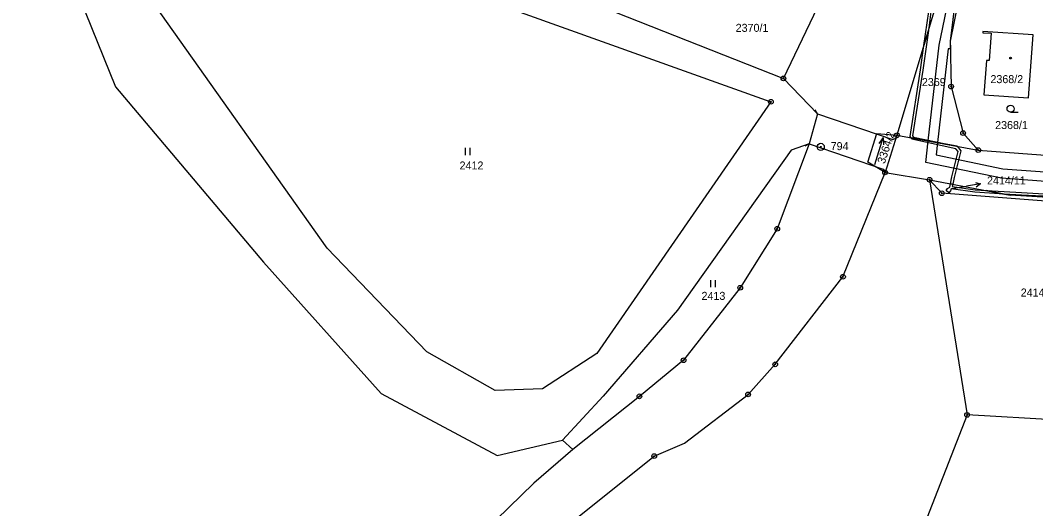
# Model space of a CAD drawing. Extents: x -755819 to -753140, y -1169796 to -1166000.
# Drawn here: x -755808.9 to -755593.2, y -1168194.5 to -1168090.8 of the extents above; entities that cross this region are included whole.
import ezdxf

# ---------------------------------------------------------------- set-up
doc = ezdxf.new("R2010")
doc.units = 0
for name, color, linetype in [('Vrstva 1', 7, 'Continuous'), ('Vrstva 13', 7, 'Continuous'), ('Vrstva 16', 7, 'Continuous'), ('Vrstva 17', 7, 'Continuous'), ('Vrstva 18', 7, 'Continuous'), ('Vrstva 19', 7, 'Continuous'), ('Vrstva 24', 7, 'Continuous'), ('Vrstva 25', 7, 'Continuous'), ('Vrstva 26', 7, 'Continuous'), ('Vrstva 27', 7, 'Continuous'), ('Vrstva 4', 7, 'Continuous'), ('Vrstva 6', 7, 'Continuous')]:
    doc.layers.add(name, color=color, linetype=linetype)

msp = doc.modelspace()

# ---------------------------------------------------------------- linework, layer by layer
at = {"layer": 'Vrstva 1'}
for p, q in [((-755782.2, -1168060.56), (-755649.47, -1168108.08)), ((-755612.8, -1168082.1), (-755622.69, -1168115.19)), ((-755609.81, -1168082.33), (-755611.36, -1168095.19)), ((-755743.76, -1168139.16), (-755781.62, -1168085.7)), ((-755691.53, -1168085.44), (-755646.81, -1168103.1)), ((-755646.81, -1168103.1), (-755638.7, -1168086.23)), ((-755604.42, -1168093.15), (-755604.44, -1168093.39)), ((-755604.44, -1168093.39), (-755602.7, -1168093.52)), ((-755593.74, -1168093.87), (-755604.42, -1168093.15)), ((-755602.7, -1168093.52), (-755603.13, -1168099.31)), ((-755611.36, -1168095.19), (-755611.19, -1168104.84)), ((-755594.73, -1168107.23), (-755593.74, -1168093.87)), ((-755603.66, -1168099.27), (-755604.21, -1168106.57)), ((-755603.13, -1168099.31), (-755603.66, -1168099.27)), ((-755646.81, -1168103.1), (-755639.56, -1168110.66)), ((-755611.19, -1168104.84), (-755608.64, -1168114.72)), ((-755604.21, -1168106.57), (-755594.73, -1168107.23)), ((-755649.47, -1168108.08), (-755686.43, -1168161.59)), ((-755639.56, -1168110.66), (-755641.34, -1168117.04)), ((-755622.69, -1168115.19), (-755625.23, -1168123.08)), ((-755622.69, -1168115.19), (-755605.43, -1168118.33)), ((-755608.64, -1168114.72), (-755605.43, -1168118.33)), ((-755641.34, -1168117.04), (-755648.12, -1168135.05)), ((-755641.34, -1168117.04), (-755645.14, -1168118.36)), ((-755645.14, -1168118.36), (-755669.31, -1168152.33)), ((-755605.43, -1168118.33), (-755588.19, -1168119.65)), ((-755634.16, -1168145.26), (-755625.23, -1168123.08)), ((-755625.23, -1168123.08), (-755615.77, -1168124.65)), ((-755615.77, -1168124.65), (-755598.64, -1168127.91)), ((-755615.77, -1168124.65), (-755613.17, -1168127.5)), ((-755615.77, -1168124.65), (-755607.79, -1168174.61)), ((-755573.74, -1168130.54), (-755613.17, -1168127.5)), ((-755573.66, -1168129.55), (-755598.64, -1168127.91)), ((-755648.12, -1168135.05), (-755655.99, -1168147.58)), ((-755722.58, -1168161.23), (-755743.76, -1168139.16)), ((-755648.55, -1168163.86), (-755634.16, -1168145.26)), ((-755655.99, -1168147.58), (-755668.02, -1168162.99)), ((-755669.31, -1168152.33), (-755685.09, -1168170.63)), ((-755708.02, -1168169.41), (-755722.58, -1168161.23)), ((-755686.43, -1168161.59), (-755698.02, -1168169.09)), ((-755668.02, -1168162.99), (-755677.41, -1168170.66)), ((-755654.33, -1168170.24), (-755648.55, -1168163.86)), ((-755698.02, -1168169.09), (-755708.02, -1168169.41)), ((-755685.09, -1168170.63), (-755693.73, -1168179.96)), ((-755677.41, -1168170.66), (-755691.52, -1168181.99)), ((-755667.82, -1168180.58), (-755654.33, -1168170.24)), ((-755607.79, -1168174.61), (-755635.8, -1168246.36)), ((-755577.27, -1168176.31), (-755607.79, -1168174.61)), ((-755674.26, -1168183.37), (-755667.82, -1168180.58)), ((-755700.39, -1168204.18), (-755674.26, -1168183.37))]:
    msp.add_line(p, q, dxfattribs=at)
at = {"layer": 'Vrstva 13'}
for p, q in [((-755808.93, -1168054.38), (-755788.71, -1168104.9)), ((-755788.71, -1168104.9), (-755757.26, -1168142.14)), ((-755757.26, -1168142.14), (-755732.3, -1168170.07)), ((-755732.3, -1168170.07), (-755707.61, -1168183.26)), ((-755707.61, -1168183.26), (-755693.73, -1168179.96)), ((-755691.52, -1168181.99), (-755699.87, -1168189.14)), ((-755693.73, -1168179.96), (-755691.52, -1168181.99)), ((-755699.87, -1168189.14), (-755724.27, -1168212.8))]:
    msp.add_line(p, q, dxfattribs=at)
at = {"layer": 'Vrstva 16'}
for p in [(-755604.96, -1168125.54), (-755611.03, -1168126.5)]:
    msp.add_line(p, (-755607.92, -1168126.01), dxfattribs=at)
msp.add_lwpolyline([(-755606.02, -1168125.21), (-755604.96, -1168125.54), (-755605.87, -1168126.19)], dxfattribs=at)
at = {"layer": 'Vrstva 24'}
for centre, radius in [((-755646.81, -1168103.1), 0.5), ((-755646.81, -1168103.1), 0.1), ((-755611.19, -1168104.84), 0.5), ((-755611.19, -1168104.84), 0.1), ((-755649.47, -1168108.08), 0.5), ((-755649.47, -1168108.08), 0.1), ((-755622.69, -1168115.19), 0.5), ((-755622.69, -1168115.19), 0.1), ((-755608.64, -1168114.72), 0.5), ((-755608.64, -1168114.72), 0.1), ((-755638.88, -1168117.65), 0.75), ((-755638.88, -1168117.65), 0.1), ((-755605.43, -1168118.33), 0.5), ((-755605.43, -1168118.33), 0.1), ((-755625.23, -1168123.08), 0.5), ((-755625.23, -1168123.08), 0.1), ((-755615.77, -1168124.65), 0.5), ((-755615.77, -1168124.65), 0.1), ((-755613.17, -1168127.5), 0.5), ((-755613.17, -1168127.5), 0.1), ((-755648.12, -1168135.05), 0.5), ((-755648.12, -1168135.05), 0.1), ((-755634.16, -1168145.26), 0.5), ((-755634.16, -1168145.26), 0.1), ((-755655.99, -1168147.58), 0.5), ((-755655.99, -1168147.58), 0.1), ((-755668.02, -1168162.99), 0.5), ((-755668.02, -1168162.99), 0.1), ((-755648.55, -1168163.86), 0.5), ((-755648.55, -1168163.86), 0.1), ((-755677.41, -1168170.66), 0.5), ((-755677.41, -1168170.66), 0.1), ((-755654.33, -1168170.24), 0.5), ((-755654.33, -1168170.24), 0.1), ((-755607.79, -1168174.61), 0.5), ((-755607.79, -1168174.61), 0.1), ((-755674.26, -1168183.37), 0.5), ((-755674.26, -1168183.37), 0.1)]:
    msp.add_circle(centre, radius, dxfattribs=at)
at = {"layer": 'Vrstva 25'}
for p, q in [((-755598.56, -1168110.3), (-755596.96, -1168110.3)), ((-755714.33, -1168119.39), (-755714.33, -1168117.89)), ((-755713.33, -1168119.39), (-755713.33, -1168117.89)), ((-755662.27, -1168147.45), (-755662.27, -1168145.95)), ((-755661.27, -1168147.45), (-755661.27, -1168145.95))]:
    msp.add_line(p, q, dxfattribs=at)
for points in [[(-755627.42, -1168121.38), (-755625.6, -1168115.66), (-755626.53, -1168116.94)], [(-755625.6, -1168115.66), (-755625.58, -1168117.24)]]:
    msp.add_lwpolyline(points, dxfattribs=at)
for centre, radius in [((-755598.56, -1168098.8), 0.175), ((-755598.56, -1168109.55), 0.75)]:
    msp.add_circle(centre, radius, dxfattribs=at)
at = {"layer": 'Vrstva 26'}
for p, q in [((-755639.56, -1168110.66), (-755640.08, -1168109.81)), ((-755641.34, -1168117.04), (-755642.24, -1168117.48)), ((-755623.56, -1168116.07), (-755622.66, -1168115.64)), ((-755625.65, -1168122.36), (-755625.13, -1168123.21))]:
    msp.add_line(p, q, dxfattribs=at)
at = {"layer": 'Vrstva 27'}
for p, q in [((-755613.76, -1168096.03), (-755611.73, -1168086.45)), ((-755616.98, -1168096.09), (-755615.96, -1168088.87)), ((-755615.48, -1168088.97), (-755616.03, -1168092.92)), ((-755610.39, -1168087.18), (-755611.36, -1168095.19)), ((-755616.03, -1168092.92), (-755617.22, -1168101.39)), ((-755616.98, -1168096.09), (-755616.03, -1168092.92)), ((-755616.03, -1168092.92), (-755616.98, -1168096.09)), ((-755611.36, -1168095.19), (-755611.33, -1168096.83)), ((-755617.72, -1168101.31), (-755616.98, -1168096.09)), ((-755616.07, -1168116.39), (-755613.76, -1168096.03)), ((-755611.83, -1168096.79), (-755614.1, -1168116.75)), ((-755611.33, -1168096.83), (-755611.83, -1168096.79)), ((-755619.88, -1168115.42), (-755617.72, -1168101.31)), ((-755617.22, -1168101.39), (-755619.36, -1168115.32)), ((-755619.7, -1168115.73), (-755619.88, -1168115.42)), ((-755619.52, -1168116.04), (-755619.7, -1168115.73)), ((-755609.88, -1168117.52), (-755619.7, -1168115.73)), ((-755619.7, -1168115.73), (-755609.88, -1168117.52)), ((-755610.17, -1168118.06), (-755619.52, -1168116.04)), ((-755619.36, -1168115.32), (-755619.2, -1168115.6)), ((-755619.2, -1168115.6), (-755609.88, -1168117.52)), ((-755616.59, -1168120.98), (-755616.07, -1168116.39)), ((-755614.1, -1168116.75), (-755614.39, -1168119.38)), ((-755614.39, -1168119.38), (-755600.23, -1168122.3)), ((-755611.01, -1168124.04), (-755609.68, -1168118.64)), ((-755609.14, -1168118.52), (-755610.53, -1168124.16)), ((-755609.68, -1168118.64), (-755610.17, -1168118.06)), ((-755609.88, -1168117.52), (-755609.14, -1168118.52)), ((-755600.51, -1168124.28), (-755616.59, -1168120.98)), ((-755600.23, -1168122.3), (-755587.81, -1168123.24)), ((-755611.48, -1168126.18), (-755611.33, -1168125.5)), ((-755611.33, -1168125.5), (-755611.01, -1168124.04)), ((-755611.33, -1168125.5), (-755610.84, -1168125.59)), ((-755610.84, -1168125.59), (-755611.33, -1168125.5)), ((-755610.84, -1168125.59), (-755610.95, -1168126.08)), ((-755610.53, -1168124.16), (-755610.84, -1168125.59)), ((-755587.93, -1168125.24), (-755600.51, -1168124.28)), ((-755612.27, -1168126.89), (-755611.94, -1168126.5)), ((-755611.65, -1168127.4), (-755612.27, -1168126.89)), ((-755611.94, -1168126.5), (-755611.48, -1168126.18)), ((-755611.33, -1168127.02), (-755611.65, -1168127.4)), ((-755611.15, -1168126.56), (-755611.33, -1168127.02)), ((-755606.12, -1168127.31), (-755611.15, -1168126.56)), ((-755610.95, -1168126.08), (-755606.06, -1168126.81)), ((-755599.92, -1168127.67), (-755606.12, -1168127.31)), ((-755606.06, -1168126.81), (-755603.75, -1168126.94)), ((-755603.75, -1168126.94), (-755599.9, -1168127.15)), ((-755603.75, -1168126.94), (-755599.92, -1168127.67)), ((-755599.92, -1168127.67), (-755603.75, -1168126.94)), ((-755596.26, -1168127.88), (-755599.92, -1168127.67)), ((-755599.9, -1168127.15), (-755596.22, -1168127.38)), ((-755590.23, -1168128.23), (-755596.26, -1168127.88)), ((-755596.22, -1168127.38), (-755590.21, -1168127.73))]:
    msp.add_line(p, q, dxfattribs=at)
at = {"layer": 'Vrstva 4'}
for p, q in [((-755609.67, -1168086.83), (-755611.36, -1168095.19)), ((-755639.56, -1168110.66), (-755623.56, -1168116.07)), ((-755641.34, -1168117.04), (-755625.65, -1168122.36))]:
    msp.add_line(p, q, dxfattribs=at)
at = {"layer": 'Vrstva 6'}
for p, q in [((-755628.88, -1168120.93), (-755626.98, -1168114.81)), ((-755626.98, -1168114.81), (-755622.69, -1168115.19)), ((-755625.23, -1168123.08), (-755628.88, -1168120.93))]:
    msp.add_line(p, q, dxfattribs=at)

# ---------------------------------------------------------------- texts
at = {"layer": 'Vrstva 16'}
msp.add_text('2414/11', height=1.7, dxfattribs=at).set_placement((-755603.56, -1168125.64))
at = {"layer": 'Vrstva 17'}
msp.add_text('794', height=1.7, dxfattribs=at).set_placement((-755636.78, -1168118.35))
at = {"layer": 'Vrstva 18'}
for s, height, p in [('2370/1', 1.7, (-755656.96, -1168093.21)), ('2369', 1.7, (-755617.4, -1168104.73)), ('2368/1', 1.7, (-755601.84, -1168113.87)), ('2412', 1.7, (-755715.61, -1168122.46)), ('2414/11', 0.1, (-755611.26, -1168126.5)), ('2413', 1.7, (-755664.21, -1168150.16)), ('2414/16', 1.7, (-755596.4, -1168149.45))]:
    msp.add_text(s, height=height, dxfattribs=at).set_placement(p)
msp.add_text('3364/2', height=1.7, rotation=71.7343, dxfattribs=at).set_placement((-755625.32, -1168121.37))
at = {"layer": 'Vrstva 19'}
msp.add_text('2368/2', height=1.7, dxfattribs=at).set_placement((-755602.84, -1168104.11))

doc.saveas('drawing.dxf')
